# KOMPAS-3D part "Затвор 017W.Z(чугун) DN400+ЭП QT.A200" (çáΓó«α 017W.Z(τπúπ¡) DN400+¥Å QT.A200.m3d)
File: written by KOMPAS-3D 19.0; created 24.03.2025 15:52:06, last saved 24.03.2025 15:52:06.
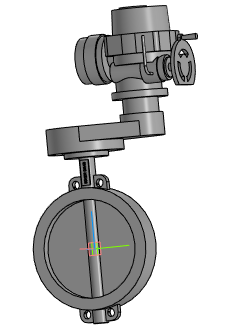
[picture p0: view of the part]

Document properties: Полное имя файла: Затвор 017W.Z(чугун) DN400+ЭП QT.A200.a3d

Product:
- Part/product: Затвор 017W.Z(чугун) DN400+ЭП QT.A200
    Масса: 318.34

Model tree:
1. Операция без истории:1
